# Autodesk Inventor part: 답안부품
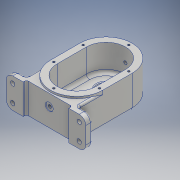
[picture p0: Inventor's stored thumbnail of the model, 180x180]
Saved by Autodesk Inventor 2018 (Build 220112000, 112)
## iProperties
Created: 2021-05
Part Number: 답안부품
Material: 알루미늄 6061
Document SubType Name: Modeling
Designer: Admin
Mass: 756.311 g
Surface Area: 582.804 cm^2
Volume: 280.115 cm^3
Density: 2.7 g/cm^3
Appearance: 알루미늄 - 평지
Author: Admin
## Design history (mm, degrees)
sketch "스케치1"
  geometry: L1 (0, 22.5)-(0, -22.5); L2 (-40, 22.5)-(-40, -22.5); L3 (40, -22.5)-(40, 22.5); A1 r 40 centre (0, 22.5) between (40, 22.5) and (-40, 22.5); A2 r 40 centre (0, -22.5) between (-40, -22.5) and (40, -22.5); 2 further points
  constraints: 8 end point, 4 point on circle, 4 tangent, 2 centre point, 1 coincident, 1 midpoint, 1 parallel, 1 vertical
  dimensions: "d0" = 80 distance between parallel lines of L3 L2; "d6" = 45 distance of L1.start L1.end
extrude "돌출1" new body sketch "스케치1" distance "d7" = 49; taper "d8" = 0 deg
sketch "스케치2"
  geometry: L1 (0, 22.5)-(0, -22.5); L2 (-30, 22.5)-(-30, -22.5); L3 (30, -22.5)-(30, 22.5); A1 r 30 centre (0, 22.5) between (30, 22.5) and (-30, 22.5); A2 r 30 centre (0, -22.5) between (-30, -22.5) and (30, -22.5); 2 further points
  constraints: 8 end point, 4 point on circle, 4 tangent, 2 centre point, 1 coincident, 1 midpoint, 1 parallel, 1 vertical
  dimensions: "d9" = 30 radius of A1; "d10" = 45 distance of L1.end L1.start
extrude "돌출2" cut sketch "스케치2" distance "d11" = 41; taper "d12" = 0 deg
sketch "스케치3"
  geometry: L1 (0, 22.5)-(0, -22.5); L2 (-26, 22.5)-(-26, -22.5); L3 (26, -22.5)-(26, 22.5); A1 r 26 centre (0, 22.5) between (26, 22.5) and (-26, 22.5); A2 r 26 centre (0, -22.5) between (-26, -22.5) and (26, -22.5); 2 further points
  constraints: 8 end point, 4 point on circle, 4 tangent, 2 centre point, 1 coincident, 1 midpoint, 1 parallel, 1 vertical
  dimensions: "d13" = 45 distance of L1.start L1.end; "d14" = 52 distance between parallel lines of L3 L2
extrude "돌출3" join sketch "스케치3" distance "d15" = 8; taper "d16" = 0 deg
sketch "스케치4"
  geometry: L1 (0, 22.5)-(0, -22.5); L2 (-26, -7.5)-(-26, -22.5); L3 (26, -22.5)-(26, -7.5); L4 (-26, -22.5)-(-26, 22.5) reference; L5 (-26, -7.5)-(26, -7.5); L6 (26, 22.5)-(26, -22.5) reference; A1 r 26 centre (0, -22.5) between (-26, -22.5) and (26, -22.5); 2 further points
  constraints: 10 end point, 2 point on circle, 2 tangent, 1 centre point, 1 coincident, 1 midpoint, 1 parallel, 1 perpendicular, 1 vertical
  dimensions: "d17" = 45 distance of L1.start L1.end; "d18" = 52 distance between parallel lines of L2 L3; "d19" = 30 distance from line of L5 L1.start
extrude "돌출4" join sketch "스케치4" distance "d20" = 3; taper "d21" = 0 deg
sketch "스케치5"
  geometry: L1 (40, -22.5)-(40, -59.5); L2 (40, -59.5)-(61, -59.5); L3 (61, -59.5)-(61, -69.5); L4 (61, -69.5)-(35, -69.5); L5 (35, -69.5)-(35, -64.5); L6 (35, -64.5)-(-35, -64.5); L7 (-35, -64.5)-(-35, -69.5); L8 (-35, -69.5)-(-61, -69.5); L9 (-61, -69.5)-(-61, -59.5); L10 (-61, -59.5)-(-40, -59.5); L11 (-40, -59.5)-(-40, -22.5); L12 (91.616, 0)-(-79.184, 0) reference; L13 (0, -95.9)-(0, 88.9) reference; A1 r 40 centre (0, -22.5) between (-40, -22.5) and (40, -22.5) reference; A2 r 40 centre (0, 22.5) between (40, 22.5) and (-40, 22.5) reference; 1 further point
  constraints: 22 end point, 8 perpendicular, 2 point on line, 2 vertical, 2 other
  dimensions: "d22" = 10 distance between parallel lines of L4 L2; "d24" = 5 distance between parallel lines of L6 L4; "d26" = 10 distance between parallel lines of L8 L10; "d27" = 122 distance between parallel lines of L3 L9; "d28" = 47 distance from line of L4 A1.centre; "d29" = 70 distance of L5.end L6.end
extrude "돌출5" join sketch "스케치5" distance "d30" = 46; taper "d31" = 0 deg
sketch "스케치6"
  geometry: L1 (35, -69.5)-(61, -69.5) reference; 3 further points
  dimensions: "d32" = 45 distance of point (0, -22.5) point (0, 22.5); "d33" = 47 distance from line of L1 point (0, -22.5)
hole "구멍1" sketch "스케치6" at (0, 22.5), (0, -22.5) diameter "d34" = 28; stored, may be unused: countersink angle "d38" = 90 deg, drill point angle "d40" = 0 deg; dims "d35" = 6, "d36" = 28, "d37" = 2, "d39" = 8
sketch "스케치7"
  geometry: L1 (61, -69.5)-(35, -69.5) reference; 2 further points
  dimensions: "d41" = 92 distance from line of L1 point (0, 22.5)
hole "구멍2" sketch "스케치7" at (0, 22.5) diameter "d42" = 22; stored, may be unused: countersink angle "d46" = 90 deg, drill point angle "d48" = 0 deg; dims "d43" = 6, "d44" = 28, "d45" = 4, "d47" = 10
sketch "스케치8"
  geometry: L1 (-22.5, 49)-(-22.5, 8) reference; L2 (-22.5, 11.58)-(-22.5, -15.933); L3 (-8.5, 0)-(-36.5, 0) reference; L4 (-12.5, 0)-(-12.5, -1); L5 (-15.5, -4)-(-22.5, -4); L6 (-12.5, 0)-(-22.5, 0); L7 (-22.5, 0)-(-22.5, -4); L8 (-22.5, 0)-(-22.5, -11) reference; A1 r 3 centre (-15.5, -1) between (-15.5, -4) and (-12.5, -1); 2 further points
  constraints: 10 end point, 5 point on line, 2 point on circle, 2 tangent, 2 vertical, 1 centre point, 1 collinear, 1 midpoint, 1 perpendicular
  dimensions: "d49" = 10 distance of point (-12.5, -4) L5.end; "d50" = 4 distance of L4.start point (-12.5, -4); "d51" = 3 radius of A1
revolve "회전1" sketch "스케치8" stored, may be unused: angle "d52" = 90 deg
sketch "스케치9"
  geometry: L1 (0, 22.5)-(0, -22.5); 8 further points
  constraints: 4 end point, 1 coincident, 1 midpoint, 1 vertical
  dimensions: "d53" = 45 distance of L1.end L1.start
hole "구멍3" sketch "스케치9" at (0, 57.5), (35, 22.5), (35, -22.5), (0, -57.5), (-35, -22.5), (-35, 22.5) diameter "d55" = 3.242; stored, may be unused: countersink angle "d59" = 90 deg, drill point angle "d61" = 118 deg; dims "d56" = 8, "d57" = 28, "d58" = 4, "d60" = 10
sketch "스케치10" dims "d62" = 40
  geometry: L1 (61, -69.5)-(35, -69.5) reference; 5 further points
  constraints: 1 vertical alignment, 6 other
  dimensions: "d63" = 92 distance from line of L1 point (0, 22.5); "d66" = 360 deg dimension on point (0, 22.5) point (0, 42.5) (derived)
hole "구멍4" sketch "스케치10" at (0, 42.5), (-17.321, 12.5), (17.321, 12.5) diameter "d68" = 3.242; stored, may be unused: countersink angle "d72" = 90 deg, drill point angle "d74" = 118 deg; dims "d69" = 8, "d70" = 28, "d71" = 4, "d73" = 10
node "작업 평면1"
sketch "스케치11"
  geometry: L1 (40, 49)-(-40, 49) reference; C1 r 6 at (0, 28); 1 further point
  constraints: 1 centre point
  dimensions: "d76" = 21 distance from line of L1 C1.centre; "d77" = 12 diameter of C1
extrude "돌출6" join sketch "스케치11" stored distance "d78" = 46; taper "d79" = 0 deg
sketch "스케치12"
  geometry: 2 further points
hole "구멍5" sketch "스케치12" at (0, 0) diameter "d80" = 4.917; stored, may be unused: countersink angle "d84" = 90 deg, drill point angle "d86" = 0 deg; dims "d81" = 20, "d82" = 28, "d83" = 4, "d85" = 20
sketch "스케치13"
  geometry: L1 (21, 0)-(0, 0) reference; L2 (21, -46)-(0, -46) reference; L3 (21, 0)-(21, -46) reference; L4 (-80, 0)-(-101, 0) reference; L5 (-101, 0)-(-101, -46) reference; L6 (-80, -46)-(-101, -46) reference; 5 further points
  dimensions: "d87" = 10 distance from line of L1 point (11, -10); "d88" = 10 distance from line of L2 point (11, -36); "d89" = 10 distance from line of L3 point (11, -36); "d90" = 10 distance from line of L3 point (11, -10); "d91" = 10 distance from line of L4 point (-91, -10); "d92" = 10 distance from line of L5 point (-91, -10); "d93" = 10 distance from line of L5 point (-91, -36); "d94" = 10 distance from line of L6 point (-91, -36)
hole "구멍6" sketch "스케치13" at (-91, -10), (-91, -36), (11, -36), (11, -10) diameter "d95" = 6.6; stored, may be unused: countersink angle "d99" = 90 deg, drill point angle "d101" = 0 deg; dims "d96" = 20, "d97" = 11, "d98" = 2, "d100" = 20
sketch "스케치14"
  geometry: L1 (-35, -69.5)-(-61, -69.5) reference; 2 further points
  constraints: 1 other
  dimensions: "d102" = 12 distance from line of L1 point (0, -57.5)
feature "엠보싱1" sketch "스케치14" dims "d103" = 0.5, "d104" = 0
sketch "스케치15"
  geometry: L1 (0, 46)-(70, 46) reference; L2 (75, 49)-(-5, 49) reference; 2 further points
  dimensions: "d106" = 21 distance from line of L2 point (35, 28)
hole "구멍7" sketch "스케치15" at (35, 28) diameter "d107" = 12; stored, may be unused: countersink angle "d111" = 90 deg, drill point angle "d113" = 0 deg; dims "d108" = 20, "d109" = 11, "d110" = 2, "d112" = 1
sketch "스케치16"
  geometry: C1 r 2.458 at (0, 0) reference; 2 further points
  constraints: 1 coincident
hole "구멍8" sketch "스케치16" at (0, 0) diameter "d114" = 4.917; stored, may be unused: countersink angle "d118" = 90 deg, drill point angle "d120" = 0 deg; dims "d115" = 20, "d116" = 11, "d117" = 2, "d119" = 20
fillet "모깎기1" dims "d121" = 10
fillet "모깎기2" dims "d122" = 0.3
fillet "모깎기3" dims "d123" = 5
chamfer "모따기1" distance "d124" = 1; stored, may be unused: second distance "d125" = 2, angle "d126" = 45 deg
fillet "모깎기4" dims "d127" = 3
fillet "모깎기5" dims "d128" = 3
fillet "모깎기6" dims "d129" = 3
fillet "모깎기7" dims "d130" = 3
fillet "모깎기8" dims "d131" = 3
node "솔리드1"
other parameters: "d75" = 65.5
